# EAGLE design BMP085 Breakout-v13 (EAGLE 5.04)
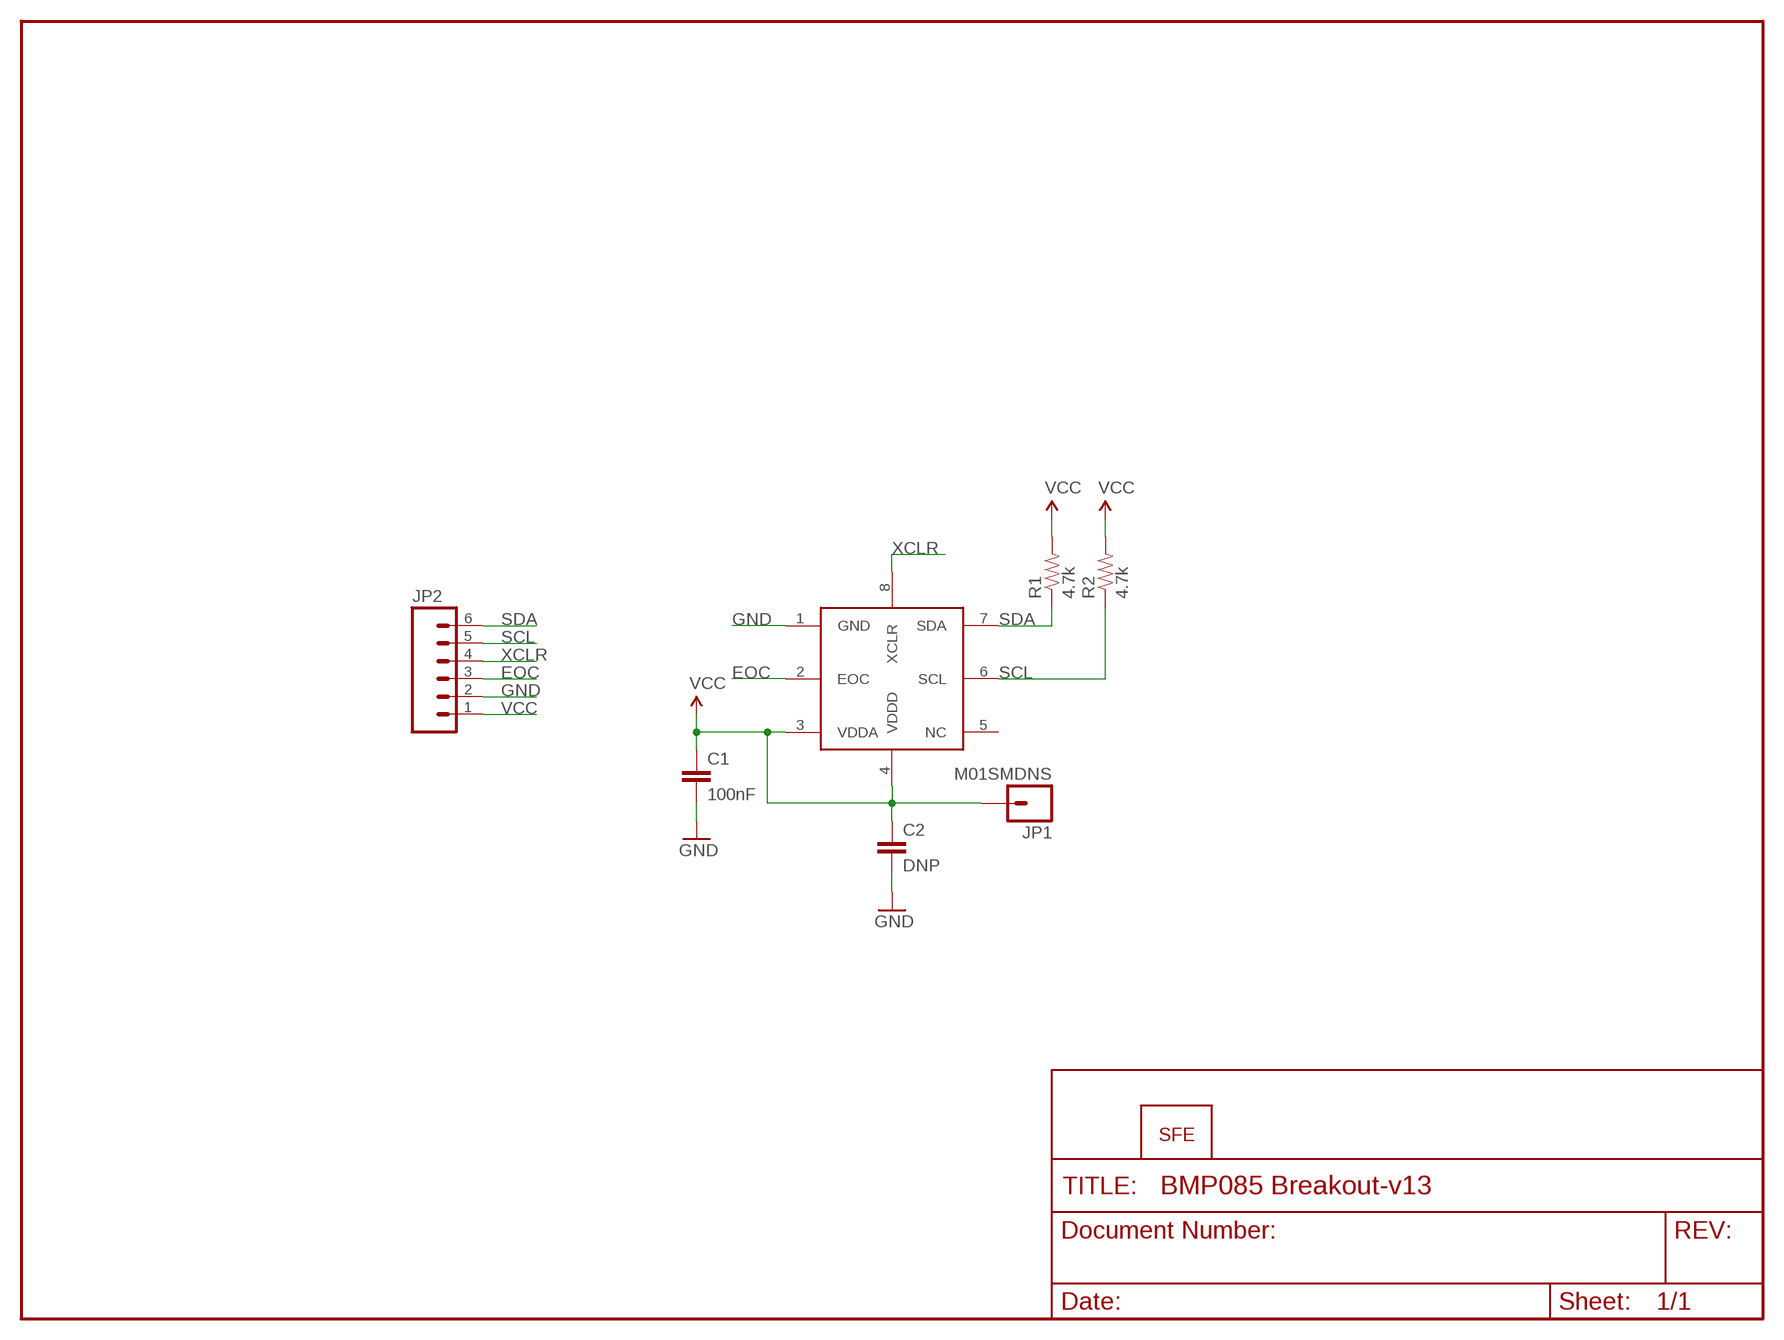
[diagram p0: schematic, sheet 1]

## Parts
C1  100nF  CAP0603-CAP  [0603-CAP]
C2  DNP  CAP0603-CAP  [0603-CAP]
JP1  M01SMDNS  [1X01NS]
JP2  M06SIP  [1X06]
JP3  LOGO-SFESK  [SFE-LOGO-FLAME]
R1  4.7k  RESISTOR0603-RES  [0603-RES]
R2  4.7k  RESISTOR0603-RES  [0603-RES]
U$1  BMP085  [BMP085]

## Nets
EOC: JP2.3 U$1.2(EOC)
GND: C1.2 C2.2 JP2.2 U$1.1(GND)
SCL: JP2.5 R2.1 U$1.6(SCL)
SDA: JP2.6 R1.1 U$1.7(SDA)
VCC: C1.1 C2.1 JP1.1 JP2.1 R1.2 R2.2 U$1.3(VDDA) U$1.4(VDDD)
XCLR: JP2.4 U$1.8(XCLR)
Unconnected: U$1.5(NC)

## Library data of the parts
C1 C2 = SparkFun:CAP: Capacitor
JP1 = SparkFun:M01: Header 1
JP2 = SparkFun:M06: Header 6 Standard 6-pin 0.1" header. Use with straight break away headers (SKU : PRT-00116), right angle break away headers (PRT-00553), swiss pins (PRT-00743), machine pins (PRT-00117), and female headers (PRT-00115). Molex polarized connector foot print use with SKU : PRT-08094 with associated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
JP3 = SparkFun:LOGO-SFE: Spark Fun Electronics PCB Logo
R1 R2 = SparkFun:RESISTOR: Resistor
U$1 = SparkFun:BMP085

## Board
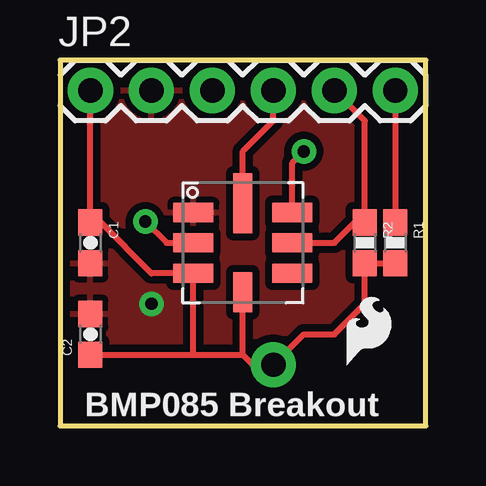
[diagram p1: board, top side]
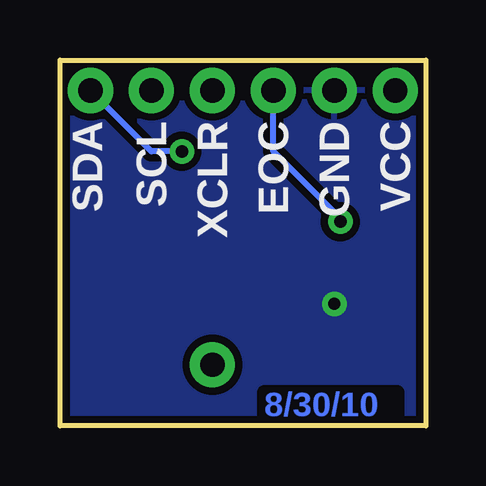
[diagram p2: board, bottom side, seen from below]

Size 15.24 x 15.24 mm. Coordinates in mm from the lower left corner, seen from the top.
Outline: 0,0 15.24,0 15.24,15.24 0,15.24 0,0
Copper layers (1*16): Top 0.035mm / dielectric 1.5mm / Bottom 0.035mm
Design rules "SparkFun": minimum track width 8mil, minimum drill 20mil, track to track 8mil, track to pad 8mil, pad to pad 8mil, via to via 8mil, smd to smd 8mil, copper to edge 9mil, drill to drill 8mil, minimum pad ring 12mil, minimum via ring 10mil, stop-mask expansion 4mil, vias tented up to drill 20mil, thermal gap 10mil

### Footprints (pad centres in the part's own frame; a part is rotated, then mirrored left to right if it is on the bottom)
0603-CAP = smd 1.1 x 1: 1 -0.85,0; 2 0.85,0
1X01NS = drill 1.016 pad 1.88 round: 1 0,0
1X06 = drill 1.016 pad 1.88 round: 1 0,0; 2 2.54,0; 3 5.08,0; 4 7.62,0; 5 10.16,0; 6 12.7,0
0603-RES = smd 1.1 x 1: 1 -0.85,0; 2 0.85,0
BMP085 = smd 1.67 x 0.8: 1 -2.065,1.27; 2 -2.065,0; 3 -2.065,-1.27; 5 2.065,-1.27; 6 2.065,0; 7 2.065,1.27 | smd 0.8 x 1.67: 4 0,-2.065 | smd 0.8 x 2.5: 8 0,1.65

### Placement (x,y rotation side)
C1  1.27,7.62 270 top
C2  1.27,3.81 90 top
JP1  8.89,2.54 0 top
JP2  1.27,13.97 0 top
JP3  11.94,2.54 0 top
R1  13.97,7.62 270 top
R2  12.7,7.62 270 top
U$1  7.62,7.62 0 top

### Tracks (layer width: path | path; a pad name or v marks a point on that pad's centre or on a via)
EOC  (via drill 0.51)
  Top 0.254: U$1.2 4.45,7.62 v3.56,8.51
  Bottom 0.254: v3.56,8.51 3.56,8.64 6.35,11.43 JP2.3
GND  (via drill 0.51)
  other vias: 3.81,5.08
  pour Top (isolate 0.305): 0,15.24 0,0 15.24,0 15.24,15.24
  pour Bottom (isolate 0.305): 0,15.24 0,0 15.24,0 15.24,15.24
SCL
  Top 0.254: U$1.6 11.43,7.62 12.28,8.47 R2.1 12.7,12.7 JP2.5
SDA  (via drill 0.51)
  Top 0.254: JP2.6 R1.1 | U$1.7 9.69,10.96 v10.16,11.43
  Bottom 0.254: v10.16,11.43 11.43,11.43 JP2.6
VCC
  Top 0.254: R1.2 R2.2 12.7,5.08 11.43,3.81 10.16,3.81 JP1.1 8.04,2.54 7.62,2.96 | JP2.1 C1.1 1.69,8.47 3.81,6.35 U$1.3 5.55,2.99 5.59,2.96 | C2.1 5.59,2.96 | 5.59,2.96 7.62,2.96 | 7.62,2.96 U$1.4
XCLR
  Top 0.254: U$1.8 7.62,11.43 8.89,12.7 JP2.4

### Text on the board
Bottom: 8/30/10
tPlace: BMP085 Breakout
bPlace: VCC | GND | EOC | XCLR | SCL | SDA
